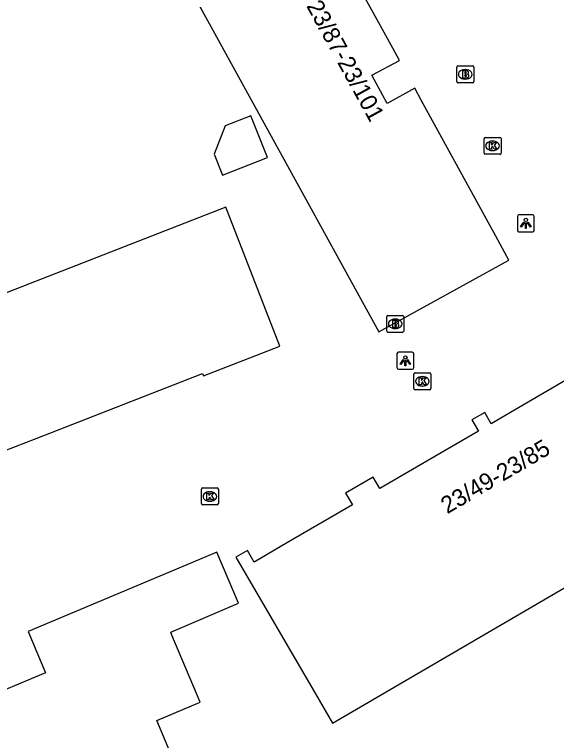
# Model space of a CAD drawing. Extents: x 161087 to 161922, y 382574 to 383873.
# Drawn here: x 161776.33 to 161808.25, y 382704.24 to 382747.01 of the extents above; entities that cross this region are included whole.
import ezdxf

# ---------------------------------------------------------------- set-up
doc = ezdxf.new("R2010")
doc.units = 0
for name, color, linetype in [('IMGEO_Brandkraan', 7, 'Continuous'), ('IMGEO_Kolk', 7, 'Continuous'), ('IMGEO_Lichtpunt', 7, 'Continuous'), ('IMGEO_Pand', 7, 'Continuous'), ('IMGEO_Pand_nummerreeks', 7, 'Continuous')]:
    doc.layers.add(name, color=color, linetype=linetype)

msp = doc.modelspace()

# ---------------------------------------------------------------- linework, layer by layer
at = {"layer": 'IMGEO_Brandkraan'}
for p, q in [((161802.377, 382743.063), (161802.377, 382743.915)), ((161802.452, 382743.989), (161803.304, 382743.989)), ((161802.865, 382743.769), (161802.89, 382743.769)), ((161803.378, 382743.915), (161803.378, 382743.063)), ((161803.304, 382742.989), (161802.452, 382742.989)), ((161802.888, 382743.209), (161802.863, 382743.209)), ((161798.253, 382728.36), (161798.253, 382729.212)), ((161798.328, 382729.286), (161799.18, 382729.286)), ((161799.254, 382729.212), (161799.254, 382728.36)), ((161798.741, 382729.066), (161798.766, 382729.066)), ((161799.18, 382728.286), (161798.328, 382728.286)), ((161798.764, 382728.506), (161798.739, 382728.506))]:
    msp.add_line(p, q, dxfattribs=at)
for points in [[(161802.377, 382743.063), (161802.377, 382743.915)], [(161802.452, 382743.989), (161803.304, 382743.989)], [(161802.725, 382743.689), (161802.725, 382743.289), (161802.938, 382743.289)], [(161802.956, 382743.689), (161802.725, 382743.689)], [(161803.378, 382743.915), (161803.378, 382743.063)], [(161802.904, 382743.608), (161802.85, 382743.608), (161802.85, 382743.532)], [(161802.85, 382743.532), (161802.903, 382743.532)], [(161802.912, 382743.456), (161802.85, 382743.456), (161802.85, 382743.375)], [(161802.85, 382743.375), (161802.912, 382743.375)], [(161803.304, 382742.989), (161802.452, 382742.989)], [(161798.253, 382728.36), (161798.253, 382729.212)], [(161798.328, 382729.286), (161799.18, 382729.286)], [(161799.254, 382729.212), (161799.254, 382728.36)], [(161798.601, 382728.986), (161798.601, 382728.586), (161798.814, 382728.586)], [(161798.832, 382728.986), (161798.601, 382728.986)], [(161798.78, 382728.905), (161798.726, 382728.905), (161798.726, 382728.829)], [(161798.726, 382728.829), (161798.779, 382728.829)], [(161798.788, 382728.753), (161798.726, 382728.753), (161798.726, 382728.672)], [(161799.18, 382728.286), (161798.328, 382728.286)], [(161798.726, 382728.672), (161798.788, 382728.672)]]:
    msp.add_lwpolyline(points, dxfattribs=at)
for centre, radius, start, end in [((161802.454, 382743.913), 0.0765, 91.552, 178.448), ((161802.454, 382743.913), 0.0765, 91.552, 178.448), ((161802.96, 382743.544), 0.145, 59.4692, 91.5367), ((161803.302, 382743.913), 0.0765, 1.552, 88.448), ((161803.302, 382743.913), 0.0765, 1.552, 88.448), ((161802.905, 382743.57), 0.0379, 267.8285, 90.9355), ((161802.913, 382743.415), 0.0404, 269.8759, 90.5077), ((161802.944, 382743.54), 0.251, 268.6676, 293.5347), ((161802.985, 382743.591), 0.0922, 285.5137, 58.1501), ((161802.99, 382743.399), 0.105, 301.3115, 78.989), ((161802.454, 382743.065), 0.0765, 181.552, 268.448), ((161802.454, 382743.065), 0.0765, 181.552, 268.448), ((161803.302, 382743.065), 0.0765, 271.552, 358.448), ((161803.302, 382743.065), 0.0765, 271.552, 358.448), ((161798.33, 382729.21), 0.0765, 91.552, 178.448), ((161798.33, 382729.21), 0.0765, 91.552, 178.448), ((161799.178, 382729.21), 0.0765, 1.552, 88.448), ((161799.178, 382729.21), 0.0765, 1.552, 88.448), ((161798.781, 382728.867), 0.0379, 267.8285, 90.9355), ((161798.789, 382728.712), 0.0404, 269.8759, 90.5077), ((161798.836, 382728.841), 0.145, 59.4692, 91.5367), ((161798.861, 382728.888), 0.0922, 285.5137, 58.1501), ((161798.866, 382728.696), 0.105, 301.3115, 78.989), ((161798.33, 382728.362), 0.0765, 181.552, 268.448), ((161798.33, 382728.362), 0.0765, 181.552, 268.448), ((161798.82, 382728.837), 0.251, 268.6676, 293.5347), ((161799.178, 382728.362), 0.0765, 271.552, 358.448), ((161799.178, 382728.362), 0.0765, 271.552, 358.448)]:
    msp.add_arc(centre, radius, start, end, dxfattribs=at)
for centre, major_axis, ratio, start_param, end_param in [((161802.864, 382743.489), (-0.387, 0.002), 0.722429, 4.712389, 7.853982), ((161802.889, 382743.489), (-0.39, 0.002), 0.717154, 1.570796, 4.712389), ((161798.74, 382728.786), (-0.387, 0.002), 0.722429, 4.712389, 7.853982), ((161798.765, 382728.786), (-0.39, 0.002), 0.717154, 1.570796, 4.712389)]:
    msp.add_ellipse(centre, major_axis=major_axis, ratio=ratio, start_param=start_param, end_param=end_param, dxfattribs=at)
at = {"layer": 'IMGEO_Kolk'}
for p, q in [((161803.987, 382738.849), (161803.987, 382739.701)), ((161804.062, 382739.775), (161804.914, 382739.775)), ((161804.475, 382739.555), (161804.5, 382739.555)), ((161804.988, 382739.701), (161804.988, 382738.849)), ((161804.498, 382738.995), (161804.473, 382738.995)), ((161804.914, 382738.775), (161804.062, 382738.775)), ((161799.851, 382724.977), (161799.851, 382725.829)), ((161799.926, 382725.903), (161800.778, 382725.903)), ((161800.852, 382725.829), (161800.852, 382724.977)), ((161800.339, 382725.683), (161800.364, 382725.683)), ((161800.778, 382724.903), (161799.926, 382724.903)), ((161800.362, 382725.123), (161800.337, 382725.123)), ((161787.335, 382718.192), (161787.335, 382719.044)), ((161787.41, 382719.118), (161788.262, 382719.118)), ((161787.823, 382718.898), (161787.848, 382718.898)), ((161788.336, 382719.044), (161788.336, 382718.192)), ((161788.262, 382718.118), (161787.41, 382718.118)), ((161787.846, 382718.338), (161787.821, 382718.338))]:
    msp.add_line(p, q, dxfattribs=at)
for points in [[(161803.987, 382738.849), (161803.987, 382739.701)], [(161804.062, 382739.775), (161804.914, 382739.775)], [(161804.308, 382739.475), (161804.431, 382739.475), (161804.431, 382739.324), (161804.561, 382739.475), (161804.725, 382739.475), (161804.579, 382739.324), (161804.732, 382739.075), (161804.58, 382739.075), (161804.495, 382739.239), (161804.431, 382739.172), (161804.431, 382739.075), (161804.308, 382739.075), (161804.308, 382739.475)], [(161804.988, 382739.701), (161804.988, 382738.849)], [(161804.914, 382738.775), (161804.062, 382738.775)], [(161799.851, 382724.977), (161799.851, 382725.829)], [(161799.926, 382725.903), (161800.778, 382725.903)], [(161800.852, 382725.829), (161800.852, 382724.977)], [(161800.172, 382725.603), (161800.295, 382725.603), (161800.295, 382725.452), (161800.425, 382725.603), (161800.589, 382725.603), (161800.443, 382725.452), (161800.596, 382725.203), (161800.444, 382725.203), (161800.359, 382725.367), (161800.295, 382725.3), (161800.295, 382725.203), (161800.172, 382725.203), (161800.172, 382725.603)], [(161800.778, 382724.903), (161799.926, 382724.903)], [(161787.335, 382718.192), (161787.335, 382719.044)], [(161787.41, 382719.118), (161788.262, 382719.118)], [(161788.336, 382719.044), (161788.336, 382718.192)], [(161787.656, 382718.818), (161787.779, 382718.818), (161787.779, 382718.667), (161787.909, 382718.818), (161788.073, 382718.818), (161787.927, 382718.667), (161788.08, 382718.418), (161787.928, 382718.418), (161787.843, 382718.582), (161787.779, 382718.515), (161787.779, 382718.418), (161787.656, 382718.418), (161787.656, 382718.818)], [(161788.262, 382718.118), (161787.41, 382718.118)]]:
    msp.add_lwpolyline(points, dxfattribs=at)
for centre, start, end in [((161804.064, 382739.699), 91.552, 178.448), ((161804.064, 382739.699), 91.552, 178.448), ((161804.912, 382739.699), 1.552, 88.448), ((161804.912, 382739.699), 1.552, 88.448), ((161804.064, 382738.851), 181.552, 268.448), ((161804.064, 382738.851), 181.552, 268.448), ((161804.912, 382738.851), 271.552, 358.448), ((161804.912, 382738.851), 271.552, 358.448), ((161799.928, 382725.827), 91.552, 178.448), ((161799.928, 382725.827), 91.552, 178.448), ((161800.776, 382725.827), 1.552, 88.448), ((161800.776, 382725.827), 1.552, 88.448), ((161799.928, 382724.979), 181.552, 268.448), ((161799.928, 382724.979), 181.552, 268.448), ((161800.776, 382724.979), 271.552, 358.448), ((161800.776, 382724.979), 271.552, 358.448), ((161787.412, 382719.042), 91.552, 178.448), ((161787.412, 382719.042), 91.552, 178.448), ((161788.26, 382719.042), 1.552, 88.448), ((161788.26, 382719.042), 1.552, 88.448), ((161787.412, 382718.194), 181.552, 268.448), ((161787.412, 382718.194), 181.552, 268.448), ((161788.26, 382718.194), 271.552, 358.448), ((161788.26, 382718.194), 271.552, 358.448)]:
    msp.add_arc(centre, 0.0765, start, end, dxfattribs=at)
for centre, major_axis, ratio, start_param, end_param in [((161804.474, 382739.275), (-0.387, 0.002), 0.722429, 4.712389, 7.853982), ((161804.499, 382739.275), (-0.39, 0.002), 0.717154, 1.570796, 4.712389), ((161800.338, 382725.403), (-0.387, 0.002), 0.722429, 4.712389, 7.853982), ((161800.363, 382725.403), (-0.39, 0.002), 0.717154, 1.570796, 4.712389), ((161787.822, 382718.618), (-0.387, 0.002), 0.722429, 4.712389, 7.853982), ((161787.847, 382718.618), (-0.39, 0.002), 0.717154, 1.570796, 4.712389)]:
    msp.add_ellipse(centre, major_axis=major_axis, ratio=ratio, start_param=start_param, end_param=end_param, dxfattribs=at)
at = {"layer": 'IMGEO_Lichtpunt'}
for p, q in [((161806.851, 382735.211), (161806.043, 382735.211)), ((161806.851, 382735.211), (161806.043, 382735.211)), ((161805.949, 382735.116), (161805.949, 382734.309)), ((161805.949, 382735.116), (161805.949, 382734.309)), ((161806.945, 382734.309), (161806.945, 382735.116)), ((161806.945, 382734.309), (161806.945, 382735.116)), ((161806.043, 382734.215), (161806.851, 382734.215)), ((161806.043, 382734.215), (161806.851, 382734.215)), ((161798.853, 382727.014), (161798.853, 382726.207)), ((161798.853, 382727.014), (161798.853, 382726.207)), ((161799.755, 382727.109), (161798.947, 382727.109)), ((161799.755, 382727.109), (161798.947, 382727.109)), ((161799.849, 382726.207), (161799.849, 382727.014)), ((161799.849, 382726.207), (161799.849, 382727.014)), ((161798.947, 382726.113), (161799.755, 382726.113)), ((161798.947, 382726.113), (161799.755, 382726.113))]:
    msp.add_line(p, q, dxfattribs=at)
for points in [[(161806.323, 382734.78), (161806.362, 382734.752), (161806.174, 382734.49), (161806.136, 382734.517), (161806.323, 382734.78)], [(161806.425, 382734.732), (161806.472, 382734.732), (161806.472, 382734.41), (161806.425, 382734.41), (161806.425, 382734.732)], [(161806.535, 382734.752), (161806.573, 382734.779), (161806.76, 382734.517), (161806.721, 382734.489), (161806.535, 382734.752)], [(161799.227, 382726.678), (161799.266, 382726.65), (161799.078, 382726.388), (161799.04, 382726.415), (161799.227, 382726.678)], [(161799.329, 382726.63), (161799.376, 382726.63), (161799.376, 382726.308), (161799.329, 382726.308), (161799.329, 382726.63)], [(161799.439, 382726.65), (161799.477, 382726.677), (161799.664, 382726.415), (161799.625, 382726.387), (161799.439, 382726.65)]]:
    msp.add_lwpolyline(points, dxfattribs=at)
for centre in [(161806.448, 382734.914), (161799.352, 382726.812)]:
    msp.add_circle(centre, 0.0994, dxfattribs=at)
for centre, start, end in [((161806.043, 382735.116), 90, 180), ((161806.043, 382735.116), 90, 180), ((161806.851, 382735.116), 0, 90), ((161806.851, 382735.116), 0, 90), ((161806.043, 382734.309), 180, 270), ((161806.043, 382734.309), 180, 270), ((161806.851, 382734.309), 270, 0), ((161806.851, 382734.309), 270, 360), ((161798.947, 382727.014), 90, 180), ((161798.947, 382727.014), 90, 180), ((161799.755, 382727.014), 0, 90), ((161799.755, 382727.014), 0, 90), ((161798.947, 382726.207), 180, 270), ((161798.947, 382726.207), 180, 270), ((161799.755, 382726.207), 270, 0), ((161799.755, 382726.207), 270, 360)]:
    msp.add_arc(centre, 0.0946, start, end, dxfattribs=at)
at = {"layer": 'IMGEO_Pand'}
for points in [[(161794.2, 382753.036), (161793.435, 382754.427), (161791.191, 382753.197), (161785.753, 382750.218), (161797.788, 382728.319), (161797.962, 382728.415), (161805.453, 382732.533), (161804.675, 382733.953), (161800.287, 382741.962), (161799.902, 382742.664), (161798.28, 382741.775), (161797.372, 382743.432), (161799.005, 382744.299), (161798.607, 382745.023), (161794.2, 382753.036)], [(161790.249, 382741.048), (161788.733, 382740.452), (161788.088, 382738.792), (161788.579, 382737.55), (161791.235, 382738.594), (161790.249, 382741.048)], [(161773.321, 382720.372), (161777.602, 382722.04), (161787.405, 382725.859), (161787.457, 382725.726), (161791.956, 382727.48), (161788.77, 382735.655), (161772.311, 382729.242)], [(161817.929, 382730.796), (161815.677, 382729.48), (161811.851, 382727.243), (161811.455, 382727.923), (161809.818, 382726.971), (161810.224, 382726.296), (161806.356, 382724.028), (161804.411, 382722.888), (161804.031, 382723.569), (161803.262, 382723.141), (161803.657, 382722.469), (161801.705, 382721.328), (161797.854, 382719.076), (161797.464, 382719.751), (161795.823, 382718.802), (161796.23, 382718.132), (161792.404, 382715.899), (161790.436, 382714.751), (161790.044, 382715.425), (161789.37, 382715.034), (161794.06, 382706.978), (161795.066, 382705.25), (161823.114, 382721.632)], [(161787.005, 382699.938), (161784.706, 382705.422), (161787.258, 382706.492), (161785.598, 382710.452), (161785.528, 382710.619), (161789.523, 382712.339), (161788.237, 382715.327), (161787.603, 382715.06), (161777.137, 382710.655), (161778.153, 382708.232), (161774.101, 382706.534), (161778.499, 382696.044)]]:
    msp.add_lwpolyline(points, dxfattribs=at)

# ---------------------------------------------------------------- texts
at = {"layer": 'IMGEO_Pand_nummerreeks'}
for s, rotation, p in [('23/87-23/101', 298.751, (161793.497, 382747.521)), ('23/49-23/85', 30.3821, (161801.818, 382717.565))]:
    msp.add_text(s, height=1, rotation=rotation, dxfattribs=at).set_placement(p)

doc.saveas('drawing.dxf')
